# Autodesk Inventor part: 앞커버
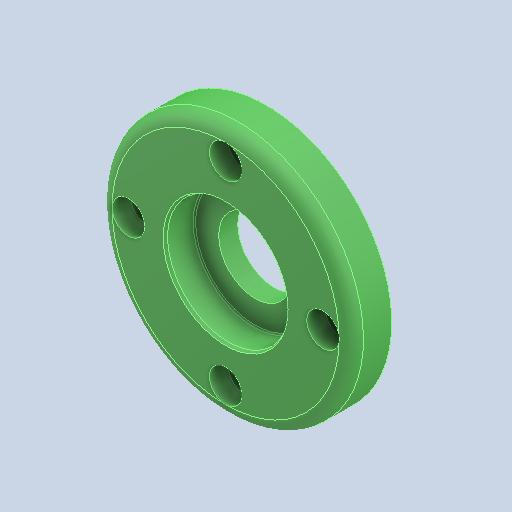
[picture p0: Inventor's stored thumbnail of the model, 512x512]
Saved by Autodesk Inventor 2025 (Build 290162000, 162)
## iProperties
Created: 2024-07
Part Number: 앞커버
Material: 알루미늄 6061
Document SubType Name: Modeling
Designer: parkm
Density: 2.71 g/cm^3
Appearance: 기본값
Author: jhkim
Sending System: Autodesk Inventor 2025
Preprocessor: ST-DEVELOPER v20
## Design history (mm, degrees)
feature "솔리드1"
node "솔리드2"
